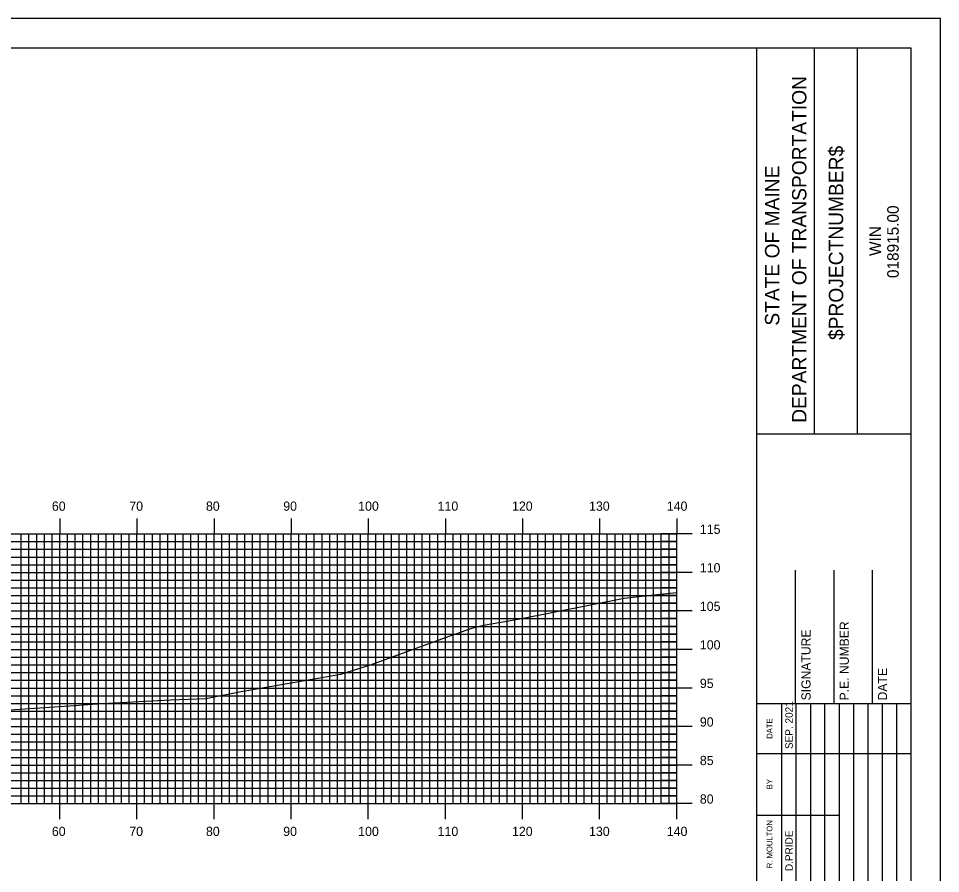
# Model space of a CAD drawing. Extents: x 1762972 to 1763315, y 442591 to 442811.
# Drawn here: x 1763191.9 to 1763311.5, y 442699.6 to 442810.5 of the extents above; entities that cross this region are included whole.
import ezdxf

# ---------------------------------------------------------------- set-up
doc = ezdxf.new("R2010")
doc.units = 0
for name, color, linetype in [('BORDER', 7, 'Continuous'), ('H_V ANNOTATION', 7, 'Continuous'), ('MAJOR', 7, 'Continuous'), ('MINOR', 7, 'Continuous'), ('PLOT BOUNDARY', 7, 'Continuous'), ('S_Roadway_Centerline', 7, 'Continuous')]:
    doc.layers.add(name, color=color, linetype=linetype)

msp = doc.modelspace()

# ---------------------------------------------------------------- linework, layer by layer
at = {"layer": 'BORDER'}
for p, q in [((1763287.69, 442596.67), (1763287.69, 442806.67)), ((1763295.15, 442756.66), (1763295.15, 442806.66)), ((1763300.74, 442756.66), (1763300.74, 442806.66)), ((1763287.69, 442756.65), (1763307.69, 442756.65)), ((1763292.69, 442721.67), (1763292.69, 442738.97)), ((1763297.69, 442721.67), (1763297.69, 442738.97)), ((1763302.69, 442721.67), (1763302.69, 442738.97)), ((1763287.69, 442721.67), (1763307.69, 442721.67))]:
    msp.add_line(p, q, dxfattribs=at)
msp.add_lwpolyline([(1762987.69, 442596.67), (1763307.69, 442596.67), (1763307.69, 442806.67), (1762987.69, 442806.67)], close=True, dxfattribs=at)
for points in [[(1763290.92, 442715.17), (1763290.92, 442721.67)], [(1763292.79, 442686.68), (1763292.79, 442721.67)], [(1763294.65, 442721.67), (1763294.65, 442686.68)], [(1763296.51, 442686.68), (1763296.51, 442721.67)], [(1763298.38, 442686.68), (1763298.38, 442721.67)], [(1763300.24, 442686.68), (1763300.24, 442721.67)], [(1763302.1, 442686.68), (1763302.1, 442721.67)], [(1763303.97, 442686.68), (1763303.97, 442721.67)], [(1763305.83, 442686.68), (1763305.83, 442721.67)], [(1763290.92, 442686.68), (1763290.92, 442720.26)], [(1763287.69, 442715.17), (1763307.69, 442715.17)], [(1763287.69, 442707.17), (1763290.92, 442707.17)], [(1763290.92, 442707.17), (1763298.38, 442707.17)]]:
    msp.add_lwpolyline(points, dxfattribs=at)
at = {"layer": 'MAJOR'}
for p, q in [((1763197.29, 442745.67), (1763197.29, 442743.67)), ((1763207.29, 442745.67), (1763207.29, 442743.67)), ((1763217.29, 442745.67), (1763217.29, 442743.67)), ((1763227.29, 442745.67), (1763227.29, 442743.67)), ((1763237.29, 442745.67), (1763237.29, 442743.67)), ((1763247.29, 442745.67), (1763247.29, 442743.67)), ((1763257.29, 442745.67), (1763257.29, 442743.67)), ((1763267.29, 442745.67), (1763267.29, 442743.67)), ((1763277.29, 442745.67), (1763277.29, 442743.67)), ((1762997.29, 442743.67), (1763277.29, 442743.67)), ((1762997.29, 442743.67), (1763277.29, 442743.67)), ((1763197.29, 442708.67), (1763197.29, 442743.67)), ((1763207.29, 442708.67), (1763207.29, 442743.67)), ((1763217.29, 442708.67), (1763217.29, 442743.67)), ((1763227.29, 442708.67), (1763227.29, 442743.67)), ((1763237.29, 442708.67), (1763237.29, 442743.67)), ((1763247.29, 442708.67), (1763247.29, 442743.67)), ((1763257.29, 442708.67), (1763257.29, 442743.67)), ((1763267.29, 442708.67), (1763267.29, 442743.67)), ((1763279.3, 442743.67), (1763275.29, 442743.67)), ((1763277.29, 442708.67), (1763277.29, 442743.67)), ((1763277.29, 442708.67), (1763277.29, 442743.67)), ((1762997.29, 442738.67), (1763277.29, 442738.67)), ((1763279.3, 442738.67), (1763275.29, 442738.67)), ((1762997.29, 442733.67), (1763277.29, 442733.67)), ((1763279.3, 442733.67), (1763275.29, 442733.67)), ((1762997.29, 442728.67), (1763277.29, 442728.67)), ((1763279.3, 442728.67), (1763275.29, 442728.67)), ((1762997.29, 442723.67), (1763277.29, 442723.67)), ((1763279.3, 442723.67), (1763275.29, 442723.67)), ((1762997.29, 442718.67), (1763277.29, 442718.67)), ((1763279.3, 442718.67), (1763275.29, 442718.67)), ((1762997.29, 442713.67), (1763277.29, 442713.67)), ((1763279.3, 442713.67), (1763275.29, 442713.67)), ((1762997.29, 442708.67), (1763277.29, 442708.67)), ((1762997.29, 442708.67), (1763277.29, 442708.67)), ((1763197.29, 442706.66), (1763197.29, 442708.67)), ((1763207.29, 442706.66), (1763207.29, 442708.67)), ((1763217.29, 442706.66), (1763217.29, 442708.67)), ((1763227.29, 442706.66), (1763227.29, 442708.67)), ((1763237.29, 442706.66), (1763237.29, 442708.67)), ((1763247.29, 442706.66), (1763247.29, 442708.67)), ((1763257.29, 442706.66), (1763257.29, 442708.67)), ((1763267.29, 442706.66), (1763267.29, 442708.67)), ((1763279.3, 442708.67), (1763275.29, 442708.67)), ((1763277.29, 442706.66), (1763277.29, 442708.67))]:
    msp.add_line(p, q, dxfattribs=at)
at = {"layer": 'MINOR'}
for p, q in [((1763192.29, 442708.67), (1763192.29, 442743.67)), ((1763193.29, 442708.67), (1763193.29, 442743.67)), ((1763194.29, 442708.67), (1763194.29, 442743.67)), ((1763195.29, 442708.67), (1763195.29, 442743.67)), ((1763196.29, 442708.67), (1763196.29, 442743.67)), ((1763198.29, 442708.67), (1763198.29, 442743.67)), ((1763199.29, 442708.67), (1763199.29, 442743.67)), ((1763200.29, 442708.67), (1763200.29, 442743.67)), ((1763201.29, 442708.67), (1763201.29, 442743.67)), ((1763202.29, 442708.67), (1763202.29, 442743.67)), ((1763203.29, 442708.67), (1763203.29, 442743.67)), ((1763204.29, 442708.67), (1763204.29, 442743.67)), ((1763205.29, 442708.67), (1763205.29, 442743.67)), ((1763206.29, 442708.67), (1763206.29, 442743.67)), ((1763208.29, 442708.67), (1763208.29, 442743.67)), ((1763209.29, 442708.67), (1763209.29, 442743.67)), ((1763210.29, 442708.67), (1763210.29, 442743.67)), ((1763211.29, 442708.67), (1763211.29, 442743.67)), ((1763212.29, 442708.67), (1763212.29, 442743.67)), ((1763213.29, 442708.67), (1763213.29, 442743.67)), ((1763214.29, 442708.67), (1763214.29, 442743.67)), ((1763215.29, 442708.67), (1763215.29, 442743.67)), ((1763216.29, 442708.67), (1763216.29, 442743.67)), ((1763218.29, 442708.67), (1763218.29, 442743.67)), ((1763219.29, 442708.67), (1763219.29, 442743.67)), ((1763220.29, 442708.67), (1763220.29, 442743.67)), ((1763221.29, 442708.67), (1763221.29, 442743.67)), ((1763222.29, 442708.67), (1763222.29, 442743.67)), ((1763223.29, 442708.67), (1763223.29, 442743.67)), ((1763224.29, 442708.67), (1763224.29, 442743.67)), ((1763225.29, 442708.67), (1763225.29, 442743.67)), ((1763226.29, 442708.67), (1763226.29, 442743.67)), ((1763228.29, 442708.67), (1763228.29, 442743.67)), ((1763229.29, 442708.67), (1763229.29, 442743.67)), ((1763230.29, 442708.67), (1763230.29, 442743.67)), ((1763231.29, 442708.67), (1763231.29, 442743.67)), ((1763232.29, 442708.67), (1763232.29, 442743.67)), ((1763233.29, 442708.67), (1763233.29, 442743.67)), ((1763234.29, 442708.67), (1763234.29, 442743.67)), ((1763235.29, 442708.67), (1763235.29, 442743.67)), ((1763236.29, 442708.67), (1763236.29, 442743.67)), ((1763238.29, 442708.67), (1763238.29, 442743.67)), ((1763239.29, 442708.67), (1763239.29, 442743.67)), ((1763240.29, 442708.67), (1763240.29, 442743.67)), ((1763241.29, 442708.67), (1763241.29, 442743.67)), ((1763242.29, 442708.67), (1763242.29, 442743.67)), ((1763243.29, 442708.67), (1763243.29, 442743.67)), ((1763244.29, 442708.67), (1763244.29, 442743.67)), ((1763245.29, 442708.67), (1763245.29, 442743.67)), ((1763246.29, 442708.67), (1763246.29, 442743.67)), ((1763248.29, 442708.67), (1763248.29, 442743.67)), ((1763249.29, 442708.67), (1763249.29, 442743.67)), ((1763250.29, 442708.67), (1763250.29, 442743.67)), ((1763251.29, 442708.67), (1763251.29, 442743.67)), ((1763252.29, 442708.67), (1763252.29, 442743.67)), ((1763253.29, 442708.67), (1763253.29, 442743.67)), ((1763254.29, 442708.67), (1763254.29, 442743.67)), ((1763255.29, 442708.67), (1763255.29, 442743.67)), ((1763256.29, 442708.67), (1763256.29, 442743.67)), ((1763258.29, 442708.67), (1763258.29, 442743.67)), ((1763259.29, 442708.67), (1763259.29, 442743.67)), ((1763260.29, 442708.67), (1763260.29, 442743.67)), ((1763261.29, 442708.67), (1763261.29, 442743.67)), ((1763262.29, 442708.67), (1763262.29, 442743.67)), ((1763263.29, 442708.67), (1763263.29, 442743.67)), ((1763264.29, 442708.67), (1763264.29, 442743.67)), ((1763265.29, 442708.67), (1763265.29, 442743.67)), ((1763266.29, 442708.67), (1763266.29, 442743.67)), ((1763268.29, 442708.67), (1763268.29, 442743.67)), ((1763269.29, 442708.67), (1763269.29, 442743.67)), ((1763270.29, 442708.67), (1763270.29, 442743.67)), ((1763271.29, 442708.67), (1763271.29, 442743.67)), ((1763272.29, 442708.67), (1763272.29, 442743.67)), ((1763273.29, 442708.67), (1763273.29, 442743.67)), ((1763274.29, 442708.67), (1763274.29, 442743.67)), ((1763275.29, 442708.67), (1763275.29, 442743.67)), ((1763276.29, 442708.67), (1763276.29, 442743.67)), ((1762997.29, 442742.67), (1763277.29, 442742.67)), ((1763277.29, 442742.67), (1763275.29, 442742.67)), ((1762997.29, 442741.67), (1763277.29, 442741.67)), ((1763277.29, 442741.67), (1763275.29, 442741.67)), ((1762997.29, 442740.67), (1763277.29, 442740.67)), ((1763277.29, 442740.67), (1763275.29, 442740.67)), ((1762997.29, 442739.67), (1763277.29, 442739.67)), ((1763277.29, 442739.67), (1763275.29, 442739.67)), ((1762997.29, 442737.67), (1763277.29, 442737.67)), ((1763277.29, 442737.67), (1763275.29, 442737.67)), ((1762997.29, 442736.67), (1763277.29, 442736.67)), ((1763277.29, 442736.67), (1763275.29, 442736.67)), ((1762997.29, 442735.67), (1763277.29, 442735.67)), ((1763277.29, 442735.67), (1763275.29, 442735.67)), ((1762997.29, 442734.67), (1763277.29, 442734.67)), ((1763277.29, 442734.67), (1763275.29, 442734.67)), ((1762997.29, 442732.67), (1763277.29, 442732.67)), ((1763277.29, 442732.67), (1763275.29, 442732.67)), ((1762997.29, 442731.67), (1763277.29, 442731.67)), ((1763277.29, 442731.67), (1763275.29, 442731.67)), ((1762997.29, 442730.67), (1763277.29, 442730.67)), ((1763277.29, 442730.67), (1763275.29, 442730.67)), ((1762997.29, 442729.67), (1763277.29, 442729.67)), ((1763277.29, 442729.67), (1763275.29, 442729.67)), ((1762997.29, 442727.67), (1763277.29, 442727.67)), ((1762997.29, 442726.67), (1763277.29, 442726.67)), ((1763277.29, 442727.67), (1763275.29, 442727.67)), ((1763277.29, 442726.67), (1763275.29, 442726.67)), ((1762997.29, 442725.67), (1763277.29, 442725.67)), ((1763277.29, 442725.67), (1763275.29, 442725.67)), ((1762997.29, 442724.67), (1763277.29, 442724.67)), ((1763277.29, 442724.67), (1763275.29, 442724.67)), ((1762997.29, 442722.67), (1763277.29, 442722.67)), ((1763277.29, 442722.67), (1763275.29, 442722.67)), ((1762997.29, 442721.67), (1763277.29, 442721.67)), ((1762997.29, 442720.67), (1763277.29, 442720.67)), ((1763277.29, 442721.67), (1763275.29, 442721.67)), ((1763277.29, 442720.67), (1763275.29, 442720.67)), ((1762997.29, 442719.67), (1763277.29, 442719.67)), ((1763277.29, 442719.67), (1763275.29, 442719.67)), ((1762997.29, 442717.67), (1763277.29, 442717.67)), ((1763277.29, 442717.67), (1763275.29, 442717.67)), ((1762997.29, 442716.67), (1763277.29, 442716.67)), ((1763277.29, 442716.67), (1763275.29, 442716.67)), ((1762997.29, 442715.67), (1763277.29, 442715.67)), ((1762997.29, 442714.67), (1763277.29, 442714.67)), ((1763277.29, 442715.67), (1763275.29, 442715.67)), ((1763277.29, 442714.67), (1763275.29, 442714.67)), ((1762997.29, 442712.67), (1763277.29, 442712.67)), ((1763277.29, 442712.67), (1763275.29, 442712.67)), ((1762997.29, 442711.67), (1763277.29, 442711.67)), ((1763277.29, 442711.67), (1763275.29, 442711.67)), ((1762997.29, 442710.67), (1763277.29, 442710.67)), ((1763277.29, 442710.67), (1763275.29, 442710.67)), ((1762997.29, 442709.67), (1763277.29, 442709.67)), ((1763277.29, 442709.67), (1763275.29, 442709.67))]:
    msp.add_line(p, q, dxfattribs=at)
at = {"layer": 'PLOT BOUNDARY'}
msp.add_lwpolyline([(1762971.51, 442590.55), (1763311.51, 442590.55), (1763311.51, 442810.55), (1762971.51, 442810.55)], close=True, dxfattribs=at)
at = {"layer": 'S_Roadway_Centerline'}
msp.add_lwpolyline([(1763184.32, 442720.42), (1763198.54, 442721.35), (1763202.74, 442721.67), (1763211.64, 442722.13), (1763216.23, 442722.32), (1763220.81, 442723.24), (1763233.74, 442725.47), (1763237.6, 442726.68), (1763247.29, 442730.21), (1763250.74, 442731.43), (1763252.22, 442731.83), (1763256.71, 442732.61), (1763270.48, 442735.34), (1763274.72, 442735.79), (1763277.29, 442736.06)], dxfattribs=at)

# ---------------------------------------------------------------- texts
at = {"layer": 'BORDER'}
for s, height, p in [('DEPARTMENT OF TRANSPORTATION', 1.8635, (1763294.11, 442758.08)), ('$PROJECTNUMBER$', 1.8635, (1763298.88, 442768.82)), ('STATE OF MAINE', 1.8635, (1763290.6, 442770.69)), ('018915.00', 1.491, (1763306.08, 442776.86)), ('WIN', 1.491, (1763303.77, 442779.73)), ('P.E. NUMBER', 1.1811, (1763299.61, 442722.06)), ('SIGNATURE', 1.181, (1763294.65, 442722.06)), ('DATE', 1.181, (1763304.57, 442722.06)), ('SEP. 2021', 0.969, (1763292.34, 442715.76)), ('DATE', 0.743, (1763289.7, 442717.08)), ('BY', 0.743, (1763289.7, 442710.54)), ('R. MOULTON', 0.745, (1763289.7, 442700.28)), ('D.PRIDE', 0.969, (1763292.34, 442699.92))]:
    msp.add_text(s, height=height, rotation=90, dxfattribs=at).set_placement(p)
at = {"layer": 'H_V ANNOTATION'}
for s, p in [('60', (1763196.26, 442746.67)), ('70', (1763206.3, 442746.67)), ('80', (1763216.24, 442746.67)), ('90', (1763226.26, 442746.67)), ('100', (1763235.98, 442746.67)), ('110', (1763246.28, 442746.67)), ('120', (1763255.93, 442746.67)), ('130', (1763265.92, 442746.67)), ('140', (1763276, 442746.67)), ('115', (1763280.29, 442743.67)), ('110', (1763280.29, 442738.67)), ('105', (1763280.29, 442733.67)), ('100', (1763280.29, 442728.67)), ('95', (1763280.29, 442723.67)), ('90', (1763280.29, 442718.67)), ('85', (1763280.29, 442713.67)), ('80', (1763280.29, 442708.67)), ('60', (1763196.26, 442704.47)), ('70', (1763206.3, 442704.47)), ('80', (1763216.24, 442704.47)), ('90', (1763226.26, 442704.47)), ('100', (1763235.98, 442704.47)), ('110', (1763246.28, 442704.47)), ('120', (1763255.93, 442704.47)), ('130', (1763265.92, 442704.47)), ('140', (1763276, 442704.47))]:
    msp.add_text(s, height=1.2, dxfattribs=at).set_placement(p)

doc.saveas('drawing.dxf')
